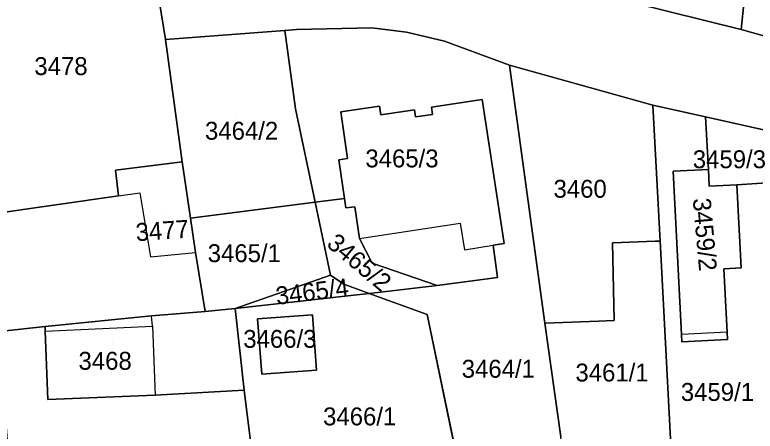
# Model space of a CAD drawing. Extents: x -262657 to -261595, y -1238015 to -1237156.
# Drawn here: x -262269.2 to -262186.5, y -1237540.4 to -1237493.9 of the extents above; entities that cross this region are included whole.
import ezdxf

# ---------------------------------------------------------------- set-up
doc = ezdxf.new("R2010")
doc.units = 0
for name, color, linetype in [('body_kn', 7, 'Continuous'), ('kladpar_druhypozemkov', 7, 'Continuous'), ('kladpar_hranice', 7, 'Continuous'), ('kladpar_parcelnecisla', 7, 'Continuous'), ('kladpar_plochy', 7, 'Continuous'), ('zappar_hrandruhpozemk', 7, 'Continuous')]:
    doc.layers.add(name, color=color, linetype=linetype)

msp = doc.modelspace()

# ---------------------------------------------------------------- linework, layer by layer
at = {"layer": 'body_kn'}
for p, q in [((-262239.05, -1237495.67), (-262239.05, -1237495.67)), ((-262239.05, -1237495.67), (-262239.05, -1237495.67)), ((-262237.74, -1237495.57), (-262237.74, -1237495.57)), ((-262229.33, -1237495.37), (-262229.33, -1237495.37)), ((-262225.44, -1237495.84), (-262225.44, -1237495.84)), ((-262188.04, -1237495.55), (-262188.04, -1237495.55)), ((-262188.04, -1237495.55), (-262188.04, -1237495.55)), ((-262252.4, -1237496.67), (-262252.4, -1237496.67)), ((-262252.4, -1237496.67), (-262252.4, -1237496.67)), ((-262221.2, -1237496.85), (-262221.2, -1237496.85)), ((-262213.95, -1237499.54), (-262213.95, -1237499.54)), ((-262213.95, -1237499.54), (-262213.95, -1237499.54)), ((-262228.48, -1237504.1), (-262228.48, -1237504.1)), ((-262217.01, -1237503.36), (-262217.01, -1237503.36)), ((-262197.92, -1237504), (-262197.92, -1237504)), ((-262197.92, -1237504), (-262197.92, -1237504)), ((-262237.87, -1237504.41), (-262237.87, -1237504.41)), ((-262232.81, -1237504.75), (-262232.81, -1237504.75)), ((-262232.81, -1237504.75), (-262232.81, -1237504.75)), ((-262224.56, -1237504.52), (-262224.56, -1237504.52)), ((-262222.67, -1237504.21), (-262222.67, -1237504.21)), ((-262228.31, -1237505.09), (-262228.31, -1237505.09)), ((-262224.44, -1237505.32), (-262224.44, -1237505.32)), ((-262222.54, -1237505.03), (-262222.54, -1237505.03)), ((-262192.03, -1237505.31), (-262192.03, -1237505.31)), ((-262250.53, -1237510.33), (-262250.53, -1237510.33)), ((-262233.01, -1237510.09), (-262233.01, -1237510.09)), ((-262232.05, -1237509.94), (-262232.05, -1237509.94)), ((-262257.99, -1237511.25), (-262257.99, -1237511.25)), ((-262195.66, -1237511.38), (-262195.66, -1237511.38)), ((-262195.66, -1237511.38), (-262195.66, -1237511.38)), ((-262191.72, -1237511.18), (-262191.72, -1237511.18)), ((-262191.72, -1237511.18), (-262191.72, -1237511.18)), ((-262191.63, -1237513.05), (-262191.63, -1237513.05)), ((-262188.55, -1237512.9), (-262188.55, -1237512.9)), ((-262255.25, -1237513.78), (-262255.25, -1237513.78)), ((-262257.63, -1237514.11), (-262257.63, -1237514.11)), ((-262257.63, -1237514.11), (-262257.63, -1237514.11)), ((-262235.66, -1237514.83), (-262235.66, -1237514.83)), ((-262235.66, -1237514.83), (-262235.66, -1237514.83)), ((-262232.4, -1237514.41), (-262232.4, -1237514.41)), ((-262232.25, -1237515.47), (-262232.25, -1237515.47)), ((-262231.22, -1237515.36), (-262231.22, -1237515.36)), ((-262249.59, -1237516.63), (-262249.59, -1237516.63)), ((-262249.59, -1237516.63), (-262249.59, -1237516.63)), ((-262219.46, -1237517.18), (-262219.46, -1237517.18)), ((-262230.71, -1237518.89), (-262230.71, -1237518.89)), ((-262230.71, -1237518.89), (-262230.71, -1237518.89)), ((-262215.76, -1237519.65), (-262215.76, -1237519.65)), ((-262214.54, -1237519.46), (-262214.54, -1237519.46)), ((-262202.43, -1237519.38), (-262202.43, -1237519.38)), ((-262197.68, -1237519.2), (-262197.68, -1237519.2)), ((-262197.1, -1237519.2), (-262197.1, -1237519.2)), ((-262249.02, -1237520.46), (-262249.02, -1237520.46)), ((-262218.98, -1237520.16), (-262218.98, -1237520.16)), ((-262254.07, -1237520.95), (-262254.07, -1237520.95)), ((-262229.29, -1237521.66), (-262229.29, -1237521.66)), ((-262189.98, -1237522.27), (-262189.98, -1237522.27)), ((-262188.07, -1237522.17), (-262188.07, -1237522.17)), ((-262233.94, -1237522.97), (-262233.94, -1237522.97)), ((-262215.28, -1237523.23), (-262215.28, -1237523.23)), ((-262232.45, -1237524), (-262232.45, -1237524)), ((-262222.02, -1237524.13), (-262222.02, -1237524.13)), ((-262232, -1237525.29), (-262232, -1237525.29)), ((-262229.63, -1237525.03), (-262229.63, -1237525.03)), ((-262247.96, -1237527.06), (-262247.96, -1237527.06)), ((-262244.6, -1237526.72), (-262244.6, -1237526.72)), ((-262244.6, -1237526.72), (-262244.6, -1237526.72)), ((-262253.94, -1237527.54), (-262253.94, -1237527.54)), ((-262242.11, -1237527.88), (-262242.11, -1237527.88)), ((-262242.11, -1237527.88), (-262242.11, -1237527.88)), ((-262235.96, -1237527.43), (-262235.96, -1237527.43)), ((-262223.16, -1237527.38), (-262223.16, -1237527.38)), ((-262204.01, -1237528.11), (-262204.01, -1237528.11)), ((-262202.25, -1237528.05), (-262202.25, -1237528.05)), ((-262265.84, -1237528.72), (-262265.84, -1237528.72)), ((-262253.85, -1237528.7), (-262253.85, -1237528.7)), ((-262253.85, -1237528.7), (-262253.85, -1237528.7)), ((-262210, -1237528.34), (-262210, -1237528.34)), ((-262265.82, -1237529.24), (-262265.82, -1237529.24)), ((-262265.82, -1237529.24), (-262265.82, -1237529.24)), ((-262194.72, -1237529.61), (-262194.72, -1237529.61)), ((-262194.72, -1237529.61), (-262194.72, -1237529.61)), ((-262189.61, -1237529.35), (-262189.61, -1237529.35)), ((-262194.68, -1237530.43), (-262194.68, -1237530.43)), ((-262189.57, -1237530.17), (-262189.57, -1237530.17)), ((-262235.5, -1237533.59), (-262235.5, -1237533.59)), ((-262241.63, -1237534.06), (-262241.63, -1237534.06)), ((-262243.58, -1237535.83), (-262243.58, -1237535.83)), ((-262265.52, -1237536.87), (-262265.52, -1237536.87)), ((-262253.53, -1237536.4), (-262253.53, -1237536.4))]:
    msp.add_line(p, q, dxfattribs=at)
at = {"layer": 'kladpar_druhypozemkov'}
for p, q in [((-262263.72, -1237498.49), (-262263.72, -1237498.49)), ((-262244.4, -1237505.33), (-262244.4, -1237505.33)), ((-262224.54, -1237508.78), (-262224.54, -1237508.78)), ((-262188.26, -1237508.59), (-262188.26, -1237508.59)), ((-262206.05, -1237512.71), (-262206.05, -1237512.71)), ((-262252.36, -1237515.71), (-262252.36, -1237515.71)), ((-262190.82, -1237518.62), (-262190.82, -1237518.62)), ((-262243.56, -1237519.21), (-262243.56, -1237519.21)), ((-262232.92, -1237519.16), (-262232.92, -1237519.16)), ((-262234.69, -1237524.59), (-262234.69, -1237524.59)), ((-262239.22, -1237528.64), (-262239.22, -1237528.64)), ((-262258.34, -1237530.53), (-262258.34, -1237530.53)), ((-262216.35, -1237531.84), (-262216.35, -1237531.84)), ((-262202.61, -1237532.79), (-262202.61, -1237532.79)), ((-262190.14, -1237535.52), (-262190.14, -1237535.52)), ((-262230.2, -1237537.69), (-262230.2, -1237537.69))]:
    msp.add_line(p, q, dxfattribs=at)
at = {"layer": 'kladpar_hranice'}
msp.add_line((-262194.72, -1237529.61), (-262195.66, -1237511.38), dxfattribs=at)
for points in [[(-262275, -1237481.7), (-262253.7, -1237488.58), (-262252.4, -1237496.67), (-262250.53, -1237510.33), (-262257.99, -1237511.25), (-262257.63, -1237514.11), (-262271.94, -1237516.16), (-262272.6, -1237508.36), (-262274, -1237495.67), (-262274.04, -1237494.95), (-262274.65, -1237486.63), (-262275, -1237481.7)], [(-262176.23, -1237498.85), (-262188.04, -1237495.55), (-262187.47, -1237489.81), (-262186.79, -1237482.88), (-262173.3, -1237481.5), (-262172.82, -1237486.91), (-262162.65, -1237485.9), (-262161.92, -1237493.89), (-262170.83, -1237494.36), (-262174.64, -1237493.24), (-262176.23, -1237498.85)], [(-262233.77, -1237484.32), (-262227.97, -1237485.78), (-262217.58, -1237488.31), (-262203.08, -1237491.83), (-262200.25, -1237492.52), (-262188.04, -1237495.55), (-262176.23, -1237498.85), (-262172.44, -1237499.78), (-262154.86, -1237504.09), (-262127.96, -1237510.84), (-262123.16, -1237511.93), (-262108.89, -1237515.33), (-262096.16, -1237518.4), (-262086.35, -1237520.76), (-262075.41, -1237523.56), (-262071.48, -1237524.52), (-262067.34, -1237525.53), (-262049.86, -1237529.82), (-262034.62, -1237534.07), (-262030.05, -1237535.39)], [(-262184.55, -1237506.98), (-262192.03, -1237505.31), (-262197.92, -1237504), (-262213.95, -1237499.54), (-262221.2, -1237496.85), (-262225.44, -1237495.84), (-262229.33, -1237495.37), (-262237.74, -1237495.57), (-262239.05, -1237495.67), (-262252.4, -1237496.67), (-262253.7, -1237488.58)], [(-262188.04, -1237495.55), (-262200.25, -1237492.52), (-262200.26, -1237491.4), (-262194.65, -1237490.53), (-262187.47, -1237489.81), (-262188.04, -1237495.55)], [(-262252.4, -1237496.67), (-262239.05, -1237495.67), (-262237.87, -1237504.41), (-262235.66, -1237514.83), (-262249.59, -1237516.63), (-262250.53, -1237510.33), (-262252.4, -1237496.67)], [(-262239.05, -1237495.67), (-262237.74, -1237495.57), (-262229.33, -1237495.37), (-262225.44, -1237495.84), (-262221.2, -1237496.85), (-262213.95, -1237499.54), (-262210, -1237528.34), (-262208.22, -1237541.03)], [(-262219.93, -1237542.86), (-262223.16, -1237527.38), (-262229.63, -1237525.03), (-262222.02, -1237524.13), (-262215.28, -1237523.23), (-262215.76, -1237519.65), (-262214.54, -1237519.46), (-262217.01, -1237503.36), (-262222.67, -1237504.21), (-262222.54, -1237505.03), (-262224.44, -1237505.32), (-262224.56, -1237504.52), (-262228.31, -1237505.09), (-262228.48, -1237504.1), (-262232.81, -1237504.75), (-262232.05, -1237509.94), (-262233.01, -1237510.09), (-262232.4, -1237514.41), (-262235.66, -1237514.83), (-262237.87, -1237504.41), (-262239.05, -1237495.67)], [(-262213.95, -1237499.54), (-262197.92, -1237504), (-262197.1, -1237519.2), (-262197.68, -1237519.2), (-262202.43, -1237519.38), (-262202.25, -1237528.05), (-262204.01, -1237528.11), (-262210, -1237528.34), (-262213.95, -1237499.54)], [(-262232.81, -1237504.75), (-262228.48, -1237504.1), (-262228.31, -1237505.09), (-262224.56, -1237504.52), (-262224.44, -1237505.32), (-262222.54, -1237505.03), (-262222.67, -1237504.21), (-262217.01, -1237503.36), (-262214.54, -1237519.46), (-262215.76, -1237519.65), (-262215.28, -1237523.23), (-262222.02, -1237524.13), (-262229.29, -1237521.66), (-262230.71, -1237518.89), (-262231.22, -1237515.36), (-262232.25, -1237515.47), (-262232.4, -1237514.41), (-262233.01, -1237510.09), (-262232.05, -1237509.94), (-262232.81, -1237504.75)], [(-262197.92, -1237504), (-262192.03, -1237505.31), (-262191.72, -1237511.18), (-262195.66, -1237511.38), (-262194.72, -1237529.61)], [(-262189.61, -1237529.35), (-262189.98, -1237522.27), (-262188.07, -1237522.17), (-262188.55, -1237512.9), (-262184.64, -1237512.65), (-262184.91, -1237529.32), (-262185.04, -1237542.92), (-262190.29, -1237543.75), (-262195.85, -1237543.12), (-262195.87, -1237542.69), (-262197.1, -1237519.2), (-262197.92, -1237504)], [(-262191.72, -1237511.18), (-262192.03, -1237505.31), (-262184.55, -1237506.98), (-262184.29, -1237507.03), (-262184.4, -1237512.64), (-262184.64, -1237512.65), (-262188.55, -1237512.9), (-262191.63, -1237513.05), (-262191.72, -1237511.18)], [(-262271.94, -1237516.16), (-262257.63, -1237514.11), (-262257.99, -1237511.25), (-262250.53, -1237510.33), (-262249.59, -1237516.63), (-262249.02, -1237520.46), (-262247.96, -1237527.06), (-262253.94, -1237527.54), (-262265.84, -1237528.72), (-262270.96, -1237529.28), (-262271.61, -1237520.83), (-262271.76, -1237518.62), (-262271.94, -1237516.16)], [(-262195.66, -1237511.38), (-262191.72, -1237511.18), (-262191.63, -1237513.05), (-262188.55, -1237512.9), (-262188.07, -1237522.17), (-262189.98, -1237522.27), (-262189.61, -1237529.35)], [(-262249.59, -1237516.63), (-262235.66, -1237514.83), (-262233.94, -1237522.97), (-262244.6, -1237526.72), (-262247.96, -1237527.06), (-262249.02, -1237520.46), (-262249.59, -1237516.63)], [(-262235.66, -1237514.83), (-262232.4, -1237514.41), (-262232.25, -1237515.47), (-262231.22, -1237515.36), (-262230.71, -1237518.89), (-262229.29, -1237521.66), (-262222.02, -1237524.13), (-262229.63, -1237525.03), (-262232.45, -1237524), (-262233.94, -1237522.97), (-262235.66, -1237514.83)], [(-262195.87, -1237542.69), (-262208.16, -1237541.45), (-262208.22, -1237541.03), (-262210, -1237528.34), (-262204.01, -1237528.11), (-262202.25, -1237528.05), (-262202.43, -1237519.38), (-262197.68, -1237519.2), (-262197.1, -1237519.2), (-262195.87, -1237542.69)], [(-262244.6, -1237526.72), (-262233.94, -1237522.97), (-262232.45, -1237524), (-262229.63, -1237525.03), (-262232, -1237525.29), (-262244.6, -1237526.72)], [(-262244.6, -1237526.72), (-262232, -1237525.29), (-262229.63, -1237525.03), (-262223.16, -1237527.38), (-262219.93, -1237542.86), (-262224.18, -1237543.63), (-262234.38, -1237546.3)], [(-262244.6, -1237526.72), (-262243.58, -1237535.83), (-262253.53, -1237536.4), (-262265.52, -1237536.87), (-262265.82, -1237529.24), (-262265.84, -1237528.72), (-262253.94, -1237527.54), (-262247.96, -1237527.06), (-262244.6, -1237526.72)], [(-262234.38, -1237546.3), (-262233.82, -1237549.1), (-262238.68, -1237550.01), (-262241.76, -1237550.48), (-262243.58, -1237535.83), (-262244.6, -1237526.72)], [(-262242.11, -1237527.88), (-262235.96, -1237527.43), (-262235.5, -1237533.59), (-262241.63, -1237534.06), (-262242.11, -1237527.88)], [(-262235.5, -1237533.59), (-262235.96, -1237527.43), (-262242.11, -1237527.88), (-262241.63, -1237534.06), (-262235.5, -1237533.59)], [(-262241.76, -1237550.48), (-262269.47, -1237549.04), (-262270.96, -1237529.28), (-262265.84, -1237528.72), (-262265.82, -1237529.24), (-262265.52, -1237536.87), (-262253.53, -1237536.4), (-262243.58, -1237535.83), (-262241.76, -1237550.48)], [(-262189.61, -1237529.35), (-262189.57, -1237530.17), (-262194.68, -1237530.43), (-262194.72, -1237529.61)], [(-262194.72, -1237529.61), (-262194.68, -1237530.43), (-262189.57, -1237530.17), (-262189.61, -1237529.35)]]:
    msp.add_lwpolyline(points, dxfattribs=at)
at = {"layer": 'kladpar_plochy'}
for p, q in [((-262244.6, -1237526.72), (-262232, -1237525.29)), ((-262232, -1237525.29), (-262229.63, -1237525.03)), ((-262229.63, -1237525.03), (-262223.16, -1237527.38)), ((-262243.58, -1237535.83), (-262244.6, -1237526.72)), ((-262235.96, -1237527.43), (-262242.11, -1237527.88)), ((-262242.11, -1237527.88), (-262241.63, -1237534.06)), ((-262235.5, -1237533.59), (-262235.96, -1237527.43)), ((-262223.16, -1237527.38), (-262219.93, -1237542.86)), ((-262241.63, -1237534.06), (-262235.5, -1237533.59)), ((-262241.76, -1237550.48), (-262243.58, -1237535.83))]:
    msp.add_line(p, q, dxfattribs=at)
for points in [[(-262274.37, -1237475.76), (-262249.82, -1237480.64), (-262233.77, -1237484.32), (-262227.97, -1237485.78), (-262217.58, -1237488.31), (-262203.08, -1237491.83), (-262200.25, -1237492.52), (-262188.04, -1237495.55), (-262176.23, -1237498.85), (-262172.44, -1237499.78), (-262154.86, -1237504.09), (-262127.96, -1237510.84), (-262123.16, -1237511.93), (-262108.89, -1237515.33), (-262096.16, -1237518.4), (-262086.35, -1237520.76), (-262075.41, -1237523.56), (-262071.48, -1237524.52), (-262067.34, -1237525.53), (-262049.86, -1237529.82), (-262034.62, -1237534.07), (-262030.05, -1237535.39)], [(-262184.55, -1237506.98), (-262192.03, -1237505.31), (-262197.92, -1237504), (-262213.95, -1237499.54), (-262221.2, -1237496.85), (-262225.44, -1237495.84), (-262229.33, -1237495.37), (-262237.74, -1237495.57), (-262239.05, -1237495.67), (-262252.4, -1237496.67), (-262253.7, -1237488.58)], [(-262219.93, -1237542.86), (-262223.16, -1237527.38), (-262229.63, -1237525.03), (-262222.02, -1237524.13), (-262215.28, -1237523.23), (-262215.76, -1237519.65), (-262214.54, -1237519.46), (-262217.01, -1237503.36), (-262222.67, -1237504.21), (-262222.54, -1237505.03), (-262224.44, -1237505.32), (-262224.56, -1237504.52), (-262228.31, -1237505.09), (-262228.48, -1237504.1), (-262232.81, -1237504.75), (-262232.05, -1237509.94), (-262233.01, -1237510.09), (-262232.4, -1237514.41), (-262235.66, -1237514.83), (-262237.87, -1237504.41), (-262239.05, -1237495.67), (-262237.74, -1237495.57), (-262229.33, -1237495.37), (-262225.44, -1237495.84), (-262221.2, -1237496.85), (-262213.95, -1237499.54), (-262210, -1237528.34), (-262208.22, -1237541.03)]]:
    msp.add_lwpolyline(points, dxfattribs=at)
for points in [[(-262275, -1237481.7), (-262253.7, -1237488.58), (-262252.4, -1237496.67), (-262250.53, -1237510.33), (-262257.99, -1237511.25), (-262257.63, -1237514.11), (-262271.94, -1237516.16), (-262272.6, -1237508.36), (-262274, -1237495.67), (-262274.04, -1237494.95), (-262274.65, -1237486.63)], [(-262176.23, -1237498.85), (-262188.04, -1237495.55), (-262187.47, -1237489.81), (-262186.79, -1237482.88), (-262173.3, -1237481.5), (-262172.82, -1237486.91), (-262162.65, -1237485.9), (-262161.92, -1237493.89), (-262170.83, -1237494.36), (-262174.64, -1237493.24)], [(-262188.04, -1237495.55), (-262200.25, -1237492.52), (-262200.26, -1237491.4), (-262194.65, -1237490.53), (-262187.47, -1237489.81)], [(-262252.4, -1237496.67), (-262239.05, -1237495.67), (-262237.87, -1237504.41), (-262235.66, -1237514.83), (-262249.59, -1237516.63), (-262250.53, -1237510.33)], [(-262213.95, -1237499.54), (-262197.92, -1237504), (-262197.1, -1237519.2), (-262197.68, -1237519.2), (-262202.43, -1237519.38), (-262202.25, -1237528.05), (-262204.01, -1237528.11), (-262210, -1237528.34)], [(-262232.81, -1237504.75), (-262228.48, -1237504.1), (-262228.31, -1237505.09), (-262224.56, -1237504.52), (-262224.44, -1237505.32), (-262222.54, -1237505.03), (-262222.67, -1237504.21), (-262217.01, -1237503.36), (-262214.54, -1237519.46), (-262215.76, -1237519.65), (-262215.28, -1237523.23), (-262222.02, -1237524.13), (-262229.29, -1237521.66), (-262230.71, -1237518.89), (-262231.22, -1237515.36), (-262232.25, -1237515.47), (-262232.4, -1237514.41), (-262233.01, -1237510.09), (-262232.05, -1237509.94)], [(-262197.92, -1237504), (-262192.03, -1237505.31), (-262191.72, -1237511.18), (-262195.66, -1237511.38), (-262194.72, -1237529.61), (-262194.68, -1237530.43), (-262189.57, -1237530.17), (-262189.61, -1237529.35), (-262189.98, -1237522.27), (-262188.07, -1237522.17), (-262188.55, -1237512.9), (-262184.64, -1237512.65), (-262184.91, -1237529.32), (-262185.04, -1237542.92), (-262190.29, -1237543.75), (-262195.85, -1237543.12), (-262195.87, -1237542.69), (-262197.1, -1237519.2)], [(-262191.72, -1237511.18), (-262192.03, -1237505.31), (-262184.55, -1237506.98), (-262184.29, -1237507.03), (-262184.4, -1237512.64), (-262184.64, -1237512.65), (-262188.55, -1237512.9), (-262191.63, -1237513.05)], [(-262271.94, -1237516.16), (-262257.63, -1237514.11), (-262257.99, -1237511.25), (-262250.53, -1237510.33), (-262249.59, -1237516.63), (-262249.02, -1237520.46), (-262247.96, -1237527.06), (-262253.94, -1237527.54), (-262265.84, -1237528.72), (-262270.96, -1237529.28), (-262271.61, -1237520.83), (-262271.76, -1237518.62)], [(-262195.66, -1237511.38), (-262191.72, -1237511.18), (-262191.63, -1237513.05), (-262188.55, -1237512.9), (-262188.07, -1237522.17), (-262189.98, -1237522.27), (-262189.61, -1237529.35), (-262189.57, -1237530.17), (-262194.68, -1237530.43), (-262194.72, -1237529.61)], [(-262249.59, -1237516.63), (-262235.66, -1237514.83), (-262233.94, -1237522.97), (-262244.6, -1237526.72), (-262247.96, -1237527.06), (-262249.02, -1237520.46)], [(-262235.66, -1237514.83), (-262232.4, -1237514.41), (-262232.25, -1237515.47), (-262231.22, -1237515.36), (-262230.71, -1237518.89), (-262229.29, -1237521.66), (-262222.02, -1237524.13), (-262229.63, -1237525.03), (-262232.45, -1237524), (-262233.94, -1237522.97)], [(-262195.87, -1237542.69), (-262208.16, -1237541.45), (-262208.22, -1237541.03), (-262210, -1237528.34), (-262204.01, -1237528.11), (-262202.25, -1237528.05), (-262202.43, -1237519.38), (-262197.68, -1237519.2), (-262197.1, -1237519.2)], [(-262244.6, -1237526.72), (-262233.94, -1237522.97), (-262232.45, -1237524), (-262229.63, -1237525.03), (-262232, -1237525.29)], [(-262244.6, -1237526.72), (-262243.58, -1237535.83), (-262253.53, -1237536.4), (-262265.52, -1237536.87), (-262265.82, -1237529.24), (-262265.84, -1237528.72), (-262253.94, -1237527.54), (-262247.96, -1237527.06)], [(-262242.11, -1237527.88), (-262235.96, -1237527.43), (-262235.5, -1237533.59), (-262241.63, -1237534.06)], [(-262241.76, -1237550.48), (-262269.47, -1237549.04), (-262270.96, -1237529.28), (-262265.84, -1237528.72), (-262265.82, -1237529.24), (-262265.52, -1237536.87), (-262253.53, -1237536.4), (-262243.58, -1237535.83)]]:
    msp.add_lwpolyline(points, close=True, dxfattribs=at)
at = {"layer": 'zappar_hrandruhpozemk'}
for p, q in [((-262257.63, -1237514.11), (-262255.25, -1237513.78)), ((-262255.25, -1237513.78), (-262254.07, -1237520.95)), ((-262230.71, -1237518.89), (-262219.46, -1237517.18)), ((-262254.07, -1237520.95), (-262249.02, -1237520.46)), ((-262253.85, -1237528.7), (-262253.94, -1237527.54)), ((-262189.61, -1237529.35), (-262194.72, -1237529.61))]:
    msp.add_line(p, q, dxfattribs=at)
for points in [[(-262219.46, -1237517.18), (-262218.98, -1237520.16), (-262215.76, -1237519.65)], [(-262265.82, -1237529.24), (-262253.85, -1237528.7), (-262253.53, -1237536.4)]]:
    msp.add_lwpolyline(points, dxfattribs=at)

# ---------------------------------------------------------------- texts
at = {"layer": 'kladpar_parcelnecisla'}
for s, p in [('3478', (-262267.039, -1237500.64)), ('3464/2', (-262247.969, -1237507.86)), ('3465/3', (-262230.05, -1237510.95)), ('3459/3', (-262193.46, -1237511.04)), ('3460', (-262209.024, -1237514.34)), ('3465/1', (-262247.668, -1237521.53)), ('3466/3', (-262243.695, -1237531.1)), ('3468', (-262262.106, -1237533.55)), ('3464/1', (-262219.283, -1237534.44)), ('3461/1', (-262206.573, -1237534.86)), ('3459/1', (-262194.798, -1237537.03)), ('3466/1', (-262234.773, -1237539.76))]:
    msp.add_text(s, height=2, dxfattribs=at).set_placement(p)
for s, rotation, p in [('3459/2', 275, (-262193.46, -1237514.452)), ('3477', 4, (-262255.65, -1237519.205)), ('3465/2', 320, (-262234.495, -1237519.682)), ('3465/4', 7, (-262239.938, -1237526.303))]:
    msp.add_text(s, height=2, rotation=rotation, dxfattribs=at).set_placement(p)

doc.saveas('drawing.dxf')
